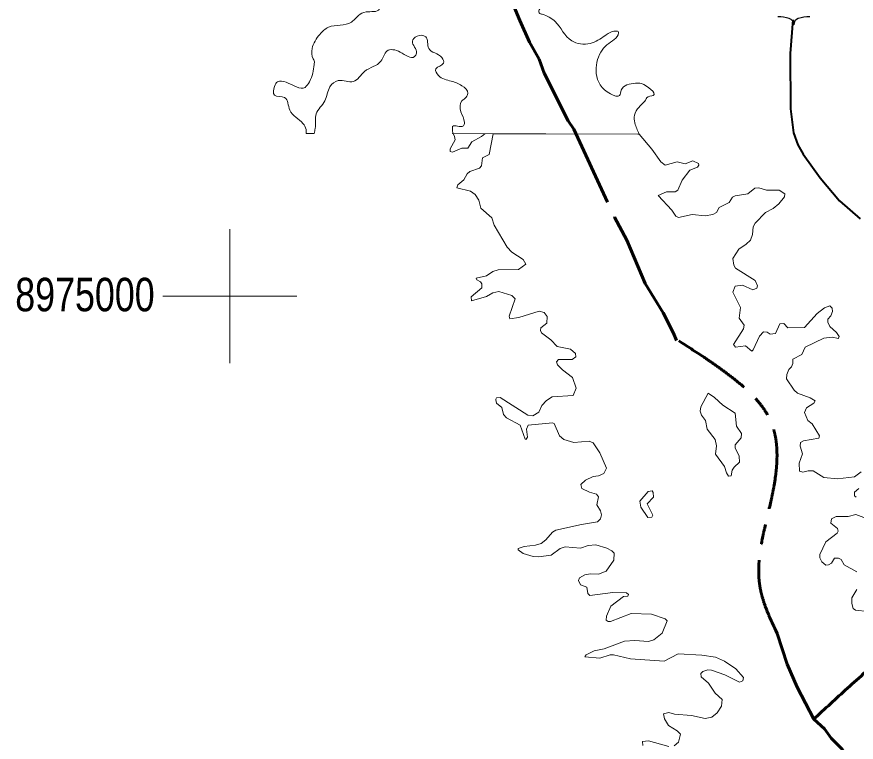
# Model space of a CAD drawing. Extents: x 553962 to 842807, y 8883888 to 9032388.
# Drawn here: x 571820 to 584357, y 8968341 to 8979171 of the extents above; entities that cross this region are included whole.
import ezdxf
from ezdxf.enums import TextEntityAlignment as Align

# ---------------------------------------------------------------- set-up
doc = ezdxf.new("R2010")
doc.units = 0
doc.header["$LTSCALE"] = 200
doc.linetypes.add('LONG_DASH_SHORT_DASH', pattern=[9.9, 6, -1.2, 1.5, -1.2])
for name, color, linetype, lineweight in [('12', 7, 'Continuous', 25), ('2', 7, 'Continuous', 13), ('25', 7, 'Continuous', 13), ('48', 7, 'Continuous', 25), ('7', 7, 'LONG_DASH_SHORT_DASH', 60)]:
    doc.layers.add(name, color=color, linetype=linetype, lineweight=lineweight)
doc.layers.add('47', color=7, linetype='Continuous')

msp = doc.modelspace()

# ---------------------------------------------------------------- linework, layer by layer
at = {"layer": '12', "lineweight": 40}
msp.add_lwpolyline([(583409.2, 8979126), (583370.9, 8978624.6), (583373.1, 8977794.5), (583422.7, 8977439.4), (583485.5, 8977258.4), (583563.7, 8977119.5), (583820.7, 8976765.3), (584108.1, 8976423.9), (584414.4, 8976152.1)], dxfattribs=at)
at = {"layer": '2'}
for p, q in [((575000, 8974000), (575000, 8976000)), ((574000, 8975000), (576000, 8975000))]:
    msp.add_line(p, q, dxfattribs=at)
at = {"layer": '25'}
for p, q in [((576139.8, 8977430.2), (576260.1, 8977429.9)), ((578329.8, 8977426), (581113.2, 8977420.6)), ((578932.9, 8977424.8), (581114.7, 8977420.6)), ((581097.2, 8977420.6), (581114.7, 8977420.6))]:
    msp.add_line(p, q, dxfattribs=at)
for points in [[(578807.8, 8977425), (578762, 8977384.2), (578616.1, 8977306), (578558.4, 8977210.3), (578467, 8977210.1), (578327, 8977150.7), (578293.1, 8977159.1), (578290.8, 8977197.4), (578364.9, 8977333.4), (578357, 8977384.6), (578337.1, 8977425.9), (578807.8, 8977425)], [(582256.6, 8972639), (582390.4, 8972456), (582418.2, 8972362.6), (582451.8, 8972314.2), (582490.4, 8972318.2), (582505.3, 8972400.8), (582532.7, 8972449.4), (582611.3, 8972522), (582607.1, 8972609.2), (582549.8, 8972736.7), (582547.7, 8972782.9), (582638.8, 8972882.9), (582643.2, 8972950.8), (582566.8, 8973059.6), (582547.5, 8973252.7), (582365, 8973371.6), (582241.8, 8973488.4), (582144.3, 8973552.1), (582036.5, 8973349.9), (582027.3, 8973284.3), (582048.5, 8973225.1), (582105.8, 8973144.3), (582131.1, 8973013.1), (582248.1, 8972859.9), (582269.4, 8972766)], [(582256.6, 8972639), (582390.4, 8972456), (582418.2, 8972362.6), (582451.8, 8972314.2), (582490.4, 8972318.2), (582505.3, 8972400.8), (582532.7, 8972449.4), (582611.3, 8972522), (582607.1, 8972609.2), (582549.8, 8972736.7), (582547.7, 8972782.9), (582638.8, 8972882.9), (582643.2, 8972950.8), (582566.8, 8973059.6), (582547.5, 8973252.7), (582365, 8973371.6), (582241.8, 8973488.4), (582144.3, 8973552.1), (582036.5, 8973349.9), (582027.3, 8973284.3), (582048.5, 8973225.1), (582105.8, 8973144.3), (582131.1, 8973013.1), (582248.1, 8972859.9), (582269.4, 8972766)], [(581237.1, 8971901.1), (581328.3, 8971997.6), (581324, 8972069.6), (581307.2, 8972094.7), (581247.3, 8972081.7), (581124.6, 8971937.6), (581139.6, 8971848.2), (581245.5, 8971693.7), (581304.9, 8971699.9), (581317.6, 8971731.5)], [(581237.1, 8971901.1), (581328.3, 8971997.6), (581324, 8972069.6), (581307.2, 8972094.7), (581247.3, 8972081.7), (581124.6, 8971937.6), (581139.6, 8971848.2), (581245.5, 8971693.7), (581304.9, 8971699.9), (581317.6, 8971731.5)]]:
    msp.add_lwpolyline(points, close=True, dxfattribs=at)
for points in [[(578611.4, 8974932.3), (578606.9, 8974988.9), (578766.5, 8975126.6), (578766.4, 8975183.8), (578747.5, 8975213.1), (578690.1, 8975245.3), (578681.8, 8975268.5), (578836.8, 8975302.7), (578932.2, 8975366.2), (579010.6, 8975391.7), (579312.2, 8975398.2), (579422.7, 8975479.2), (579384.5, 8975547), (579214.9, 8975657.2), (579145.2, 8975733), (578951.3, 8976060.9), (578917.2, 8976171.5), (578917.2, 8976171.5), (578749.8, 8976313.4), (578719.8, 8976432.4), (578664.5, 8976519.7), (578597.9, 8976566.7), (578392.8, 8976615.1), (578404.8, 8976660.8), (578496.7, 8976734.3), (578545.8, 8976827.9), (578588.3, 8976861.8), (578728.9, 8976909.1), (578762.2, 8976944.9), (578777.1, 8977063.3), (578874.7, 8977114.7), (578932.9, 8977424.8)], [(578611.4, 8974932.3), (578606.9, 8974988.9), (578766.5, 8975126.6), (578766.4, 8975183.8), (578747.5, 8975213.1), (578690.1, 8975245.3), (578681.8, 8975268.5), (578836.8, 8975302.7), (578932.2, 8975366.2), (579010.6, 8975391.7), (579312.2, 8975398.2), (579422.7, 8975479.2), (579384.5, 8975547), (579214.9, 8975657.2), (579145.2, 8975733), (578951.3, 8976060.9), (578917.2, 8976171.5), (578917.2, 8976171.5), (578749.8, 8976313.4), (578719.8, 8976432.4), (578664.5, 8976519.7), (578597.9, 8976566.7), (578392.8, 8976615.1), (578404.8, 8976660.8), (578496.7, 8976734.3), (578545.8, 8976827.9), (578588.3, 8976861.8), (578728.9, 8976909.1), (578762.2, 8976944.9), (578777.1, 8977063.3), (578874.7, 8977114.7), (578932.9, 8977424.8)], [(581114.7, 8977420.6), (581302.8, 8977195.3), (581439, 8977003.9), (581505.2, 8976955.2), (581681.2, 8977004.1), (581802.3, 8976974.5), (581916.8, 8977021), (582001.7, 8976980.5), (582005.8, 8976956.9), (581984.9, 8976923.6), (581874.3, 8976882.9), (581757.5, 8976730.1), (581691.6, 8976583.6), (581652.6, 8976555.8), (581521.7, 8976555.8), (581398.7, 8976500.6), (581602.4, 8976283.9), (581662.1, 8976192.6), (581662.1, 8976192.6), (581700.3, 8976175.7), (581908, 8976220.2), (582099.5, 8976201.1), (582214.4, 8976220.3), (582271.4, 8976250.1), (582307.6, 8976324.1), (582458.4, 8976398.8), (582508, 8976475.6), (582547.4, 8976498.9), (582737, 8976528.4), (582843.2, 8976613.2), (582902.4, 8976617.4), (583015.7, 8976581.5), (583207.5, 8976583.6), (583288.9, 8976528.1), (583288.8, 8976526.9)], [(581114.7, 8977420.6), (581302.8, 8977195.3), (581439, 8977003.9), (581505.2, 8976955.2), (581681.2, 8977004.1), (581802.3, 8976974.5), (581916.8, 8977021), (582001.7, 8976980.5), (582005.8, 8976956.9), (581984.9, 8976923.6), (581874.3, 8976882.9), (581757.5, 8976730.1), (581691.6, 8976583.6), (581652.6, 8976555.8), (581521.7, 8976555.8), (581398.7, 8976500.6), (581602.4, 8976283.9), (581662.1, 8976192.6), (581662.1, 8976192.6), (581700.3, 8976175.7), (581908, 8976220.2), (582099.5, 8976201.1), (582214.4, 8976220.3), (582271.4, 8976250.1), (582307.6, 8976324.1), (582458.4, 8976398.8), (582508, 8976475.6), (582547.4, 8976498.9), (582737, 8976528.4), (582843.2, 8976613.2), (582902.4, 8976617.4), (583015.7, 8976581.5), (583207.5, 8976583.6), (583288.9, 8976528.1), (583288.8, 8976526.9)], [(583288.8, 8976526.9), (583284.2, 8976482.2), (583201.7, 8976377.2), (583115.1, 8976307.5), (583002.1, 8976249.7), (582849.4, 8976088.5), (582817.5, 8976033.3), (582808.9, 8975922.8), (582779.2, 8975835.8), (582715.7, 8975774.3), (582605.1, 8975701.9), (582513.8, 8975564), (582530.6, 8975464.3), (582556.2, 8975419.4), (582849.3, 8975232.4), (582883.3, 8975154.1), (582874.6, 8975119.8), (582813, 8975092.3), (582657.9, 8975162.3), (582549.9, 8975147.4), (582515.9, 8975060.4), (582630.4, 8974832.8), (582607.2, 8974673.8), (582681.4, 8974567.3), (582672.8, 8974512.1), (582526.5, 8974278.7), (582552.2, 8974236.2), (582705.1, 8974259.4), (582796.4, 8974181.2), (582819.6, 8974200.3), (582913.3, 8974404.2), (582970, 8974469.5), (583025.6, 8974463.4), (583073.1, 8974433.7), (583150.7, 8974442.2), (583217.8, 8974586.7), (583276, 8974590.8), (583333.9, 8974527.2), (583584.3, 8974533.6), (583775.5, 8974739.6), (583881.7, 8974826.7), (583962.1, 8974856.3), (583998.4, 8974822.4), (584002.7, 8974769.4), (583977.2, 8974705.7), (583934.9, 8974658.8), (583930.7, 8974609.8), (583962.6, 8974546.2), (584062, 8974459.3), (584101.2, 8974395.9), (584094.7, 8974371.5)], [(583288.8, 8976526.9), (583284.2, 8976482.2), (583201.7, 8976377.2), (583115.1, 8976307.5), (583002.1, 8976249.7), (582849.4, 8976088.5), (582817.5, 8976033.3), (582808.9, 8975922.8), (582779.2, 8975835.8), (582715.7, 8975774.3), (582605.1, 8975701.9), (582513.8, 8975564), (582530.6, 8975464.3), (582556.2, 8975419.4), (582849.3, 8975232.4), (582883.3, 8975154.1), (582874.6, 8975119.8), (582813, 8975092.3), (582657.9, 8975162.3), (582549.9, 8975147.4), (582515.9, 8975060.4), (582630.4, 8974832.8), (582607.2, 8974673.8), (582681.4, 8974567.3), (582672.8, 8974512.1), (582526.5, 8974278.7), (582552.2, 8974236.2), (582705.1, 8974259.4), (582796.4, 8974181.2), (582819.6, 8974200.3), (582913.3, 8974404.2), (582970, 8974469.5), (583025.6, 8974463.4), (583073.1, 8974433.7), (583150.7, 8974442.2), (583217.8, 8974586.7), (583276, 8974590.8), (583333.9, 8974527.2), (583584.3, 8974533.6), (583775.5, 8974739.6), (583881.7, 8974826.7), (583962.1, 8974856.3), (583998.4, 8974822.4), (584002.7, 8974769.4), (583977.2, 8974705.7), (583934.9, 8974658.8), (583930.7, 8974609.8), (583962.6, 8974546.2), (584062, 8974459.3), (584101.2, 8974395.9), (584094.7, 8974371.5)], [(578975.1, 8973452.6), (578973.3, 8973461.4), (578982.8, 8973480.8), (579038.7, 8973488.1), (579452.5, 8973223.1), (579529.1, 8973212.4), (579617.1, 8973270.5), (579663.1, 8973365.4), (579733.3, 8973441.9), (579814, 8973499.2), (580130.2, 8973518.3), (580172.7, 8973628.6), (580121.6, 8973788.1), (579968.9, 8973900.6), (579894.7, 8973976.9), (579879.7, 8974019.7), (579911.8, 8974055.6), (580113, 8974056.4), (580170.5, 8974093.8), (580166.7, 8974144.9), (580087.5, 8974208.6), (579890.3, 8974249), (579794.6, 8974346.6), (579656.5, 8974453.1), (579639.6, 8974487), (579648.1, 8974525.1), (579737.1, 8974599.3), (579739.4, 8974695), (579694.8, 8974754.5), (579622.3, 8974777.8), (579316.9, 8974682.4), (579184.6, 8974659.3), (579172.4, 8974699.5), (579265.5, 8974960.7), (579214.4, 8975011.6), (579019.1, 8975068.8), (578930.3, 8975051.9), (578836.6, 8974994.6), (578611.5, 8974931), (578611.4, 8974932.3)], [(578975.1, 8973452.6), (578973.3, 8973461.4), (578982.8, 8973480.8), (579038.7, 8973488.1), (579452.5, 8973223.1), (579529.1, 8973212.4), (579617.1, 8973270.5), (579663.1, 8973365.4), (579733.3, 8973441.9), (579814, 8973499.2), (580130.2, 8973518.3), (580172.7, 8973628.6), (580121.6, 8973788.1), (579968.9, 8973900.6), (579894.7, 8973976.9), (579879.7, 8974019.7), (579911.8, 8974055.6), (580113, 8974056.4), (580170.5, 8974093.8), (580166.7, 8974144.9), (580087.5, 8974208.6), (579890.3, 8974249), (579794.6, 8974346.6), (579656.5, 8974453.1), (579639.6, 8974487), (579648.1, 8974525.1), (579737.1, 8974599.3), (579739.4, 8974695), (579694.8, 8974754.5), (579622.3, 8974777.8), (579316.9, 8974682.4), (579184.6, 8974659.3), (579172.4, 8974699.5), (579265.5, 8974960.7), (579214.4, 8975011.6), (579019.1, 8975068.8), (578930.3, 8975051.9), (578836.6, 8974994.6), (578611.5, 8974931), (578611.4, 8974932.3)], [(584094.7, 8974371.5), (584094.1, 8974369.4), (584000.2, 8974389.1), (583871.1, 8974374.2), (583595, 8974238.2), (583546.1, 8974127.9), (583408, 8974057.7), (583410, 8973996.2), (583390.8, 8973947.2), (583350.4, 8973904.1), (583321, 8973828.3), (583316.7, 8973767.3), (583431.6, 8973598.8), (583482.4, 8973550.1), (583671.6, 8973479.8), (583743.5, 8973435.3), (583724.3, 8973401.2), (583613.9, 8973333.2), (583584.4, 8973263.3), (583634.8, 8973145.1), (583699.1, 8973095.2), (583807.2, 8972917.2), (583799, 8972879.6), (583569.4, 8972838.4), (583527, 8972815), (583518.6, 8972761.7), (583556.6, 8972647.5), (583505.6, 8972506.1), (583512.2, 8972386.1), (583560.7, 8972371.1), (583638.2, 8972394.5), (583713.6, 8972394.5), (583875.1, 8972294.7), (584079, 8972273.4), (584331.8, 8972301), (584432.1, 8972379.7)], [(584094.7, 8974371.5), (584094.1, 8974369.4), (584000.2, 8974389.1), (583871.1, 8974374.2), (583595, 8974238.2), (583546.1, 8974127.9), (583408, 8974057.7), (583410, 8973996.2), (583390.8, 8973947.2), (583350.4, 8973904.1), (583321, 8973828.3), (583316.7, 8973767.3), (583431.6, 8973598.8), (583482.4, 8973550.1), (583671.6, 8973479.8), (583743.5, 8973435.3), (583724.3, 8973401.2), (583613.9, 8973333.2), (583584.4, 8973263.3), (583634.8, 8973145.1), (583699.1, 8973095.2), (583807.2, 8972917.2), (583799, 8972879.6), (583569.4, 8972838.4), (583527, 8972815), (583518.6, 8972761.7), (583556.6, 8972647.5), (583505.6, 8972506.1), (583512.2, 8972386.1), (583560.7, 8972371.1), (583638.2, 8972394.5), (583713.6, 8972394.5), (583875.1, 8972294.7), (584079, 8972273.4), (584331.8, 8972301), (584432.1, 8972379.7)], [(579428.2, 8972865), (579426, 8972861.6), (579411.7, 8972863.7), (579339.8, 8973076.5), (579133.8, 8973184.9), (579087.3, 8973233.8), (579065.8, 8973339.9), (578985.3, 8973401.7), (578975.1, 8973452.6)], [(579428.2, 8972865), (579426, 8972861.6), (579411.7, 8972863.7), (579339.8, 8973076.5), (579133.8, 8973184.9), (579087.3, 8973233.8), (579065.8, 8973339.9), (578985.3, 8973401.7), (578975.1, 8973452.6)], [(579310.3, 8971213.6), (579305.7, 8971235), (579395.2, 8971264.1), (579567.6, 8971283.5), (579652.3, 8971309), (579720.3, 8971360), (579820.2, 8971478.9), (579869.2, 8971504.5), (580251.6, 8971593.7), (580491.5, 8971629.9), (580538.3, 8971676.8), (580555.1, 8971736.2), (580536, 8971797.3), (580480.8, 8971882.8), (580506.2, 8972005.7), (580476.5, 8972043.8), (580374.6, 8972073.7), (580260.5, 8972130.7), (580245.1, 8972188.4), (580313.2, 8972254.3), (580427.7, 8972309.4), (580506.2, 8972318.1), (580588.8, 8972354), (580625.2, 8972430.6), (580529.8, 8972659.8), (580429.6, 8972808.8), (580370.3, 8972836.3), (580141.2, 8972817.2), (579988, 8972861.8), (579925.9, 8972916.6), (579843.7, 8973099.2), (579822.5, 8973110.2), (579456.8, 8973074), (579433.6, 8973012.6), (579446.1, 8972893.7), (579428.2, 8972865)], [(579310.3, 8971213.6), (579305.7, 8971235), (579395.2, 8971264.1), (579567.6, 8971283.5), (579652.3, 8971309), (579720.3, 8971360), (579820.2, 8971478.9), (579869.2, 8971504.5), (580251.6, 8971593.7), (580491.5, 8971629.9), (580538.3, 8971676.8), (580555.1, 8971736.2), (580536, 8971797.3), (580480.8, 8971882.8), (580506.2, 8972005.7), (580476.5, 8972043.8), (580374.6, 8972073.7), (580260.5, 8972130.7), (580245.1, 8972188.4), (580313.2, 8972254.3), (580427.7, 8972309.4), (580506.2, 8972318.1), (580588.8, 8972354), (580625.2, 8972430.6), (580529.8, 8972659.8), (580429.6, 8972808.8), (580370.3, 8972836.3), (580141.2, 8972817.2), (579988, 8972861.8), (579925.9, 8972916.6), (579843.7, 8973099.2), (579822.5, 8973110.2), (579456.8, 8973074), (579433.6, 8973012.6), (579446.1, 8972893.7), (579428.2, 8972865)], [(584395, 8972126.3), (584330, 8972075.8), (584330, 8972018.8), (584357.8, 8972001.5)], [(584395, 8972126.3), (584330, 8972075.8), (584330, 8972018.8), (584357.8, 8972001.5)], [(584472.4, 8971696.2), (584351.2, 8971742.2), (584236.4, 8971708.4), (584057.5, 8971710.4), (583985.8, 8971674.1), (583977.4, 8971610.7), (584075.1, 8971531.8), (584087.7, 8971489.6), (584070.5, 8971461.8), (583900.8, 8971334.4), (583811.7, 8971141.1), (583811.7, 8971092.1), (583843.3, 8971033.3), (583905.1, 8970986.2), (583943.3, 8970988.3), (583985.6, 8971013.6), (584034.9, 8971088), (584092, 8971088), (584134.5, 8971066.8), (584177.1, 8970988.3), (584368.2, 8970884.1)], [(584472.4, 8971696.2), (584351.2, 8971742.2), (584236.4, 8971708.4), (584057.5, 8971710.4), (583985.8, 8971674.1), (583977.4, 8971610.7), (584075.1, 8971531.8), (584087.7, 8971489.6), (584070.5, 8971461.8), (583900.8, 8971334.4), (583811.7, 8971141.1), (583811.7, 8971092.1), (583843.3, 8971033.3), (583905.1, 8970986.2), (583943.3, 8970988.3), (583985.6, 8971013.6), (584034.9, 8971088), (584092, 8971088), (584134.5, 8971066.8), (584177.1, 8970988.3), (584368.2, 8970884.1)], [(580309.7, 8969624.7), (580324.1, 8969646.6), (580442.8, 8969703), (580591, 8969734.8), (580897.4, 8969851.8), (581049.8, 8969860.2), (581253.8, 8969843.2), (581332.8, 8969868.9), (581457.9, 8969968.6), (581532.1, 8970155.4), (581503.8, 8970183.4), (581300.7, 8970253.2), (580995.1, 8970263.8), (580689.2, 8970142.9), (580650.8, 8970142.8), (580623.4, 8970161.8), (580627.3, 8970223.2), (580693.7, 8970370.5), (580880.2, 8970516.6), (580943.8, 8970521), (580954.3, 8970548.4), (580926, 8970569.8), (580722.7, 8970576.1), (580378.8, 8970531.6), (580349, 8970559.3), (580332.1, 8970654.5), (580240.8, 8970690.9), (580211.1, 8970756.7), (580226.1, 8970795), (580302.3, 8970841.6), (580387.3, 8970856.5), (580506.2, 8970848.1), (580624.5, 8970894.4), (580735.6, 8971058.1), (580739.9, 8971163.9), (580708, 8971200.6), (580633.5, 8971239), (580468.3, 8971285.6), (580353.1, 8971277.1), (580237.8, 8971236.7), (580009, 8971255.8), (579937.2, 8971232.5), (579937.2, 8971232.5), (579800.8, 8971134.7), (579609.6, 8971107.2), (579533.4, 8971111.5), (579380.7, 8971160.2), (579310.3, 8971213.6)], [(580309.7, 8969624.7), (580324.1, 8969646.6), (580442.8, 8969703), (580591, 8969734.8), (580897.4, 8969851.8), (581049.8, 8969860.2), (581253.8, 8969843.2), (581332.8, 8969868.9), (581457.9, 8969968.6), (581532.1, 8970155.4), (581503.8, 8970183.4), (581300.7, 8970253.2), (580995.1, 8970263.8), (580689.2, 8970142.9), (580650.8, 8970142.8), (580623.4, 8970161.8), (580627.3, 8970223.2), (580693.7, 8970370.5), (580880.2, 8970516.6), (580943.8, 8970521), (580954.3, 8970548.4), (580926, 8970569.8), (580722.7, 8970576.1), (580378.8, 8970531.6), (580349, 8970559.3), (580332.1, 8970654.5), (580240.8, 8970690.9), (580211.1, 8970756.7), (580226.1, 8970795), (580302.3, 8970841.6), (580387.3, 8970856.5), (580506.2, 8970848.1), (580624.5, 8970894.4), (580735.6, 8971058.1), (580739.9, 8971163.9), (580708, 8971200.6), (580633.5, 8971239), (580468.3, 8971285.6), (580353.1, 8971277.1), (580237.8, 8971236.7), (580009, 8971255.8), (579937.2, 8971232.5), (579937.2, 8971232.5), (579800.8, 8971134.7), (579609.6, 8971107.2), (579533.4, 8971111.5), (579380.7, 8971160.2), (579310.3, 8971213.6)], [(584364.7, 8970623), (584293.8, 8970497.2), (584291.7, 8970412.5), (584311, 8970338.1), (584347.1, 8970310.6), (584528.8, 8970293.7)], [(584364.7, 8970623), (584293.8, 8970497.2), (584291.7, 8970412.5), (584311, 8970338.1), (584347.1, 8970310.6), (584528.8, 8970293.7)], [(581636.5, 8968288.5), (581702.2, 8968341.5), (581733.9, 8968462.6), (581683.1, 8968511.3), (581551.5, 8968590), (581492, 8968691.9), (581477.3, 8968766.3), (581557.6, 8968785.3), (581642.9, 8968759.5), (581895.5, 8968738.6), (582099.5, 8968694), (582201.4, 8968717.4), (582282.1, 8968781.1), (582343.8, 8968879.1), (582356.4, 8968980.7), (582248.2, 8969074.3), (582148.5, 8969222.7), (582042.2, 8969318.6), (582035.8, 8969367.1), (582067.6, 8969395), (582142, 8969420.5), (582195.2, 8969417.7), (582396.8, 8969348.3), (582613.7, 8969237.8), (582662.3, 8969257), (582672.9, 8969307.9), (582558.3, 8969437.5), (582387.3, 8969552.8), (582256.4, 8969609.6), (582053, 8969641.4), (581695.9, 8969662.6), (581486.8, 8969550.1), (580986.3, 8969586.2), (580731.4, 8969647.8), (580680.5, 8969647.7), (580527.5, 8969596.8), (580305.1, 8969617.7), (580309.7, 8969624.7)], [(581636.5, 8968288.5), (581702.2, 8968341.5), (581733.9, 8968462.6), (581683.1, 8968511.3), (581551.5, 8968590), (581492, 8968691.9), (581477.3, 8968766.3), (581557.6, 8968785.3), (581642.9, 8968759.5), (581895.5, 8968738.6), (582099.5, 8968694), (582201.4, 8968717.4), (582282.1, 8968781.1), (582343.8, 8968879.1), (582356.4, 8968980.7), (582248.2, 8969074.3), (582148.5, 8969222.7), (582042.2, 8969318.6), (582035.8, 8969367.1), (582067.6, 8969395), (582142, 8969420.5), (582195.2, 8969417.7), (582396.8, 8969348.3), (582613.7, 8969237.8), (582662.3, 8969257), (582672.9, 8969307.9), (582558.3, 8969437.5), (582387.3, 8969552.8), (582256.4, 8969609.6), (582053, 8969641.4), (581695.9, 8969662.6), (581486.8, 8969550.1), (580986.3, 8969586.2), (580731.4, 8969647.8), (580680.5, 8969647.7), (580527.5, 8969596.8), (580305.1, 8969617.7), (580309.7, 8969624.7)], [(581170.9, 8968290.2), (581167, 8968349.8), (581254, 8968362.6), (581560.2, 8968277.7)], [(581170.9, 8968290.2), (581167, 8968349.8), (581254, 8968362.6), (581560.2, 8968277.7)]]:
    msp.add_lwpolyline(points, dxfattribs=at)
for points in [[(581113.2, 8977420.6), (581052, 8977586.8), (581044.4, 8977701), (581112.9, 8977822.7), (581219.3, 8977944.5), (581226.9, 8977959.7), (581325.8, 8977997.7), (581150.9, 8978172.7), (581059.6, 8978180.3), (580846.7, 8978073.8), (580823.9, 8977997.7), (580687, 8978020.5), (580474.1, 8978324.9), (580542.6, 8978644.5), (580633.8, 8978751), (580808.7, 8978933.6), (580808.7, 8978941.2), (580763.1, 8978956.4), (580603.4, 8978888), (580382.9, 8978773.8), (580109.1, 8978811.9), (579858.2, 8979101), (579668.1, 8979207.5), (579622.5, 8979230.4), (579622.5, 8979276), (579736.5, 8979359.7), (579827.8, 8979539.3), (579843, 8979691.5), (579827.8, 8979881.7), (579934.2, 8980049.1), (580162.3, 8980224.1), (580268.8, 8980246.9), (580337.2, 8980376.3), (580489.3, 8980460), (580595.8, 8980543.7), (580580.6, 8980650.2), (580413.3, 8980627.4), (580246, 8980619.8), (580124.3, 8980642.6), (580154.7, 8980779.6), (580626.2, 8980848), (580755.5, 8980810), (580899.9, 8980939.3), (581006.4, 8981023), (581485.5, 8981030.6), (581667.9, 8981061.1), (581765.3, 8981228.5), (581468.7, 8981160), (581309, 8981236.1), (581187.4, 8981220.9), (581187.4, 8981335), (581073.3, 8981327.4), (580989.7, 8981289.3), (580852.8, 8981297), (580701.6, 8981295.5)], [(577632.4, 8980778.5), (577561.8, 8980643.3), (577493.4, 8980521.6), (577447.7, 8980460.7), (577234.8, 8980529.2), (577120.8, 8980498.8), (577075.1, 8980559.6), (576983.9, 8980574.8), (576679.7, 8980825.9), (576603.7, 8980886.8), (576542.8, 8980879.2), (576489.6, 8980833.5), (576542.8, 8980780.3), (576679.7, 8980711.8), (576961.1, 8980361.8), (577128.4, 8980186.8), (577250, 8979973.7), (577310.9, 8979814), (577508.6, 8979654.2), (577531.4, 8979585.7), (577531.4, 8979555.2), (577371.7, 8979616.1), (577265.2, 8979631.3), (577136, 8979547.6), (577136, 8979479.2), (577151.2, 8979433.5), (577234.8, 8979380.2), (577234.8, 8979288.9), (577037.1, 8979243.3), (576923.1, 8979190), (576862.2, 8979129.2), (576816.6, 8979091.1), (576474.4, 8979015), (576345.2, 8978908.5), (576231.1, 8978695.4), (576246.3, 8978543.3), (576261.5, 8978512.8), (576261.5, 8978459.6), (576193.1, 8978200.9), (576124.6, 8978117.2), (575843.3, 8978193.3), (575714, 8978200.9), (575668.4, 8978132.4), (575668.4, 8978003), (575820.5, 8977965), (575896.5, 8977777.1), (575987.8, 8977670.5), (576094.2, 8977579.2), (576139.8, 8977487.9), (576139.8, 8977430.2)], [(576260.1, 8977429.9), (576276.7, 8977503.1), (576291.9, 8977723.8), (576421.2, 8977914), (576497.2, 8978127.1), (576618.9, 8978218.4), (576847, 8978203.2), (577014.3, 8978355.3), (577257.6, 8978507.5), (577348.9, 8978659.7), (577546.6, 8978644.5), (577759.5, 8978576), (577789.9, 8978629.2), (577729.1, 8978804.3), (577797.5, 8978880.3), (577926.8, 8978872.7), (577972.4, 8978697.7), (578170.1, 8978560.8), (578192.9, 8978477.1), (578078.9, 8978393.4), (578116.9, 8978294.5), (578307, 8978210.8), (578466.7, 8978142.3), (578557.9, 8978028.2), (578512.3, 8977952.1), (578466.7, 8977914), (578451.5, 8977754.2), (578504.7, 8977594.4), (578489.5, 8977541.2), (578329.8, 8977533.6), (578329.8, 8977465.1), (578329.8, 8977426)]]:
    msp.add_spline(points, degree=3, dxfattribs=at)
at = {"layer": '48'}
for centre, radius, start, end in [((583184.3, 8978580.8), 589.7, 72.89371, 89.90057), ((583330.1, 8979054.2), 94.4, 357.69345, 72.92955), ((583518.8, 8979054.2), 94.4, 107.07045, 182.30655), ((583664.6, 8978580.8), 589.7, 90.09943, 107.10629)]:
    msp.add_arc(centre, radius, start, end, dxfattribs=at)
at = {"layer": '7'}
for points in [[(579193.1, 8979451.5), (579330.6, 8979113.2), (579479.8, 8978793), (579620.2, 8978538.1), (579698.1, 8978330.6), (580056.8, 8977617.4), (580139.1, 8977491.6), (580748.7, 8976177.5), (580932.4, 8975835.9), (581202.8, 8975191.5), (581475, 8974750.7), (581628.9, 8974447.2), (581670.5, 8974336.1)], [(583174.4, 8969966), (583327.9, 8969505.4), (583474.7, 8969160.4), (583725.5, 8968684.8), (583883.2, 8968539.9), (583982.9, 8968403.5), (584146.9, 8968235.1), (584624.8, 8967616.6), (584992.2, 8967072.1), (585186.8, 8966825.7), (585377.2, 8966655.9), (585748.8, 8966438.6), (585960.5, 8966257.3), (586351.6, 8965976.8), (586551, 8965796.4), (587006.6, 8965310.9), (587303.1, 8964815.2), (587426.7, 8964495.3)]]:
    msp.add_lwpolyline(points, dxfattribs=at)
for points in [[(581705.4, 8974333.7), (582461.9, 8973819.1), (583080, 8973133.9), (583131.7, 8972182.4), (582921.5, 8970648.2), (583174.4, 8969966)], [(583719.8, 8968683.1), (584226, 8969147.1), (585263.8, 8970159.6), (585803.8, 8970817.7), (586453.4, 8971391.4), (587077.8, 8971939.8), (587744.3, 8972277.3), (588469.9, 8972403.9), (588728.8, 8972391.8)]]:
    msp.add_spline(points, degree=3, dxfattribs=at)

# ---------------------------------------------------------------- texts
at = {"layer": '47', "width": 0.8}
msp.add_text('8975000', height=500, dxfattribs=at).set_placement((572837.8, 8974774.3), align=Align.CENTER)

doc.saveas('drawing.dxf')
